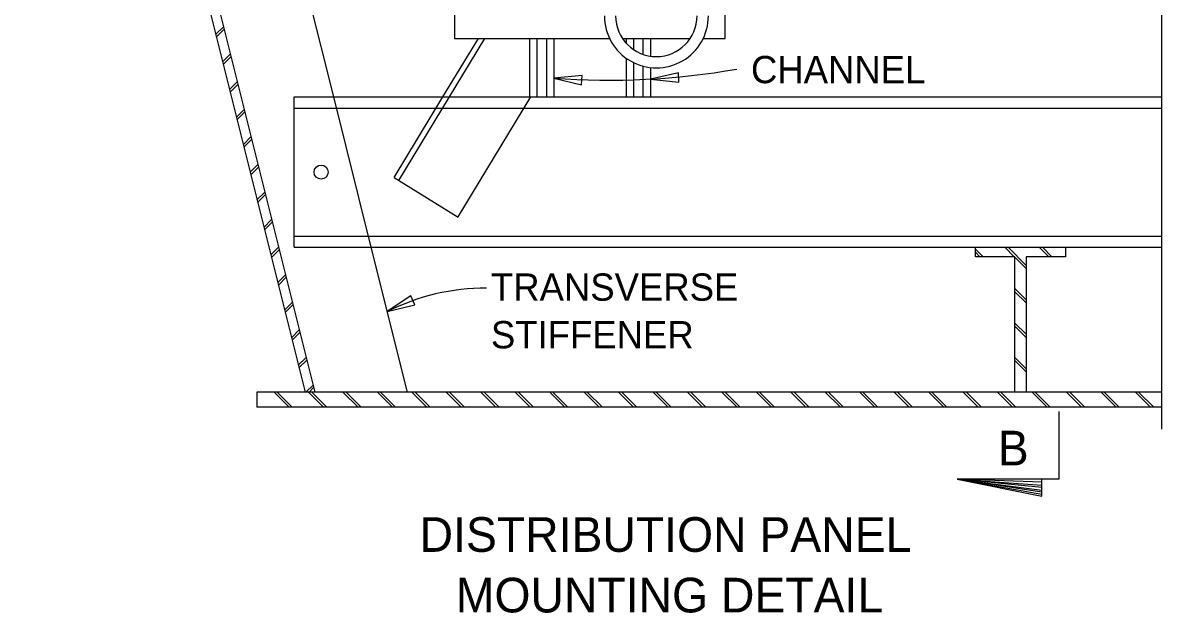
# Model space of a CAD drawing. Extents: x 927736.2 to 927809.6, y 636703.6 to 636757.7.
# Drawn here: x 927758.43 to 927774.19, y 636735.27 to 636743.33 of the extents above; entities that cross this region are included whole.
import ezdxf

# ---------------------------------------------------------------- set-up
doc = ezdxf.new("R2010")
doc.units = 0
for name, color, linetype in [('Default', 7, 'Continuous'), ('DimLines_dp', 7, 'Continuous'), ('Miscellaneous1', 7, 'Continuous'), ('Miscellaneous3', 7, 'Continuous')]:
    doc.layers.add(name, color=color, linetype=linetype)

msp = doc.modelspace()

# ---------------------------------------------------------------- linework, layer by layer
at = {"layer": 'DimLines_dp'}
for p, q in [((927772.357, 636737.056), (927771.201, 636737.099)), ((927771.201, 636737.099), (927772.357, 636737.019)), ((927772.357, 636736.985), (927771.201, 636737.099)), ((927771.201, 636737.099), (927772.357, 636736.951)), ((927772.357, 636736.92), (927771.201, 636737.099)), ((927771.201, 636737.099), (927772.357, 636736.895))]:
    msp.add_line(p, q, dxfattribs=at)
for points in [[(927774, 636737.782), (927774, 636747.055), (927773.809, 636747.055), (927774, 636747.139), (927774.191, 636747.222), (927774, 636747.222), (927774, 636756.677)], [(927772.589, 636738.024), (927772.589, 636737.099), (927771.201, 636737.099), (927772.357, 636736.867), (927772.357, 636737.099)]]:
    msp.add_lwpolyline(points, dxfattribs=at)
for points in [[(927765.688, 636742.581), (927766.067, 636742.487), (927766.077, 636742.617)], [(927767.01, 636742.568), (927767.398, 636742.524), (927767.391, 636742.654)], [(927763.409, 636739.389), (927763.788, 636739.484), (927763.736, 636739.603)]]:
    msp.add_lwpolyline(points, close=True, dxfattribs=at)
msp.add_arc((927766.454, 636752.53), 9.978, 265.6012, 280.0186, dxfattribs=at)
msp.add_ellipse((927764.747, 636736.471), major_axis=(-0.021, -3.238), ratio=0.953713, start_param=3.141601, end_param=3.59647, dxfattribs=at)
at = {"layer": 'Miscellaneous1'}
for p, q in [((927765.354, 636743.124), (927765.354, 636742.324)), ((927765.457, 636743.124), (927765.457, 636742.324)), ((927765.586, 636743.124), (927765.586, 636742.324)), ((927765.688, 636743.124), (927765.688, 636742.324)), ((927766.676, 636743.124), (927766.676, 636743.06)), ((927766.778, 636743.124), (927766.778, 636742.971)), ((927766.907, 636743.124), (927766.907, 636742.906)), ((927767.01, 636743.124), (927767.01, 636742.881)), ((927766.676, 636742.854), (927766.676, 636742.324)), ((927766.778, 636742.793), (927766.778, 636742.324)), ((927766.907, 636742.745), (927766.907, 636742.324)), ((927767.01, 636742.726), (927767.01, 636742.324))]:
    msp.add_line(p, q, dxfattribs=at)
for radius, start, end in [(0.711, 179.9955, 0.0001), (0.557, 180, 0)]:
    msp.add_arc((927767.09, 636743.432), radius, start, end, dxfattribs=at)
at = {"layer": 'Miscellaneous3'}
for p, q in [((927758.434, 636753.706), (927762.288, 636738.29)), ((927758.566, 636753.706), (927762.42, 636738.29)), ((927760.241, 636752.062), (927762.676, 636742.324)), ((927761.066, 636743.177), (927761.172, 636743.283)), ((927761.075, 636743.142), (927761.181, 636743.248)), ((927763.572, 636741.181), (927764.747, 636743.124)), ((927764.173, 636742.324), (927764.657, 636743.124)), ((927761.16, 636742.801), (927761.266, 636742.907)), ((927761.169, 636742.766), (927761.275, 636742.872)), ((927761.254, 636742.424), (927761.36, 636742.53)), ((927761.263, 636742.389), (927761.369, 636742.495)), ((927762.138, 636740.268), (927762.138, 636742.324)), ((927762.138, 636742.323), (927774, 636742.323)), ((927762.675, 636742.324), (927763.189, 636740.268)), ((927763.506, 636741.222), (927764.173, 636742.324)), ((927764.383, 636740.685), (927765.374, 636742.324)), ((927761.349, 636742.047), (927761.455, 636742.153)), ((927761.357, 636742.012), (927761.463, 636742.118)), ((927762.138, 636742.17), (927774, 636742.17)), ((927761.443, 636741.67), (927761.549, 636741.776)), ((927761.452, 636741.635), (927761.558, 636741.741)), ((927761.537, 636741.294), (927761.643, 636741.4)), ((927761.546, 636741.259), (927761.652, 636741.365)), ((927763.506, 636741.222), (927764.379, 636740.679)), ((927761.631, 636740.917), (927761.737, 636741.023)), ((927761.64, 636740.882), (927761.746, 636740.988)), ((927761.725, 636740.54), (927761.831, 636740.646)), ((927761.734, 636740.505), (927761.84, 636740.611)), ((927762.138, 636740.422), (927774, 636740.422)), ((927761.82, 636740.163), (927761.926, 636740.269)), ((927761.828, 636740.128), (927761.934, 636740.234)), ((927762.138, 636740.268), (927774, 636740.268)), ((927763.189, 636740.268), (927763.684, 636738.29)), ((927771.555, 636740.14), (927771.45, 636740.244)), ((927771.511, 636740.14), (927771.45, 636740.201)), ((927771.982, 636740.14), (927771.853, 636740.268)), ((927772.144, 636740.021), (927771.897, 636740.268)), ((927772.453, 636740.14), (927772.324, 636740.268)), ((927772.496, 636740.14), (927772.368, 636740.268)), ((927772.144, 636739.978), (927771.99, 636740.132)), ((927761.914, 636739.787), (927762.02, 636739.893)), ((927761.923, 636739.752), (927762.028, 636739.858)), ((927772.144, 636739.55), (927771.99, 636739.704)), ((927772.144, 636739.507), (927771.99, 636739.661)), ((927762.008, 636739.41), (927762.114, 636739.516)), ((927762.017, 636739.375), (927762.123, 636739.481)), ((927762.102, 636739.033), (927762.208, 636739.139)), ((927762.111, 636738.998), (927762.217, 636739.104)), ((927772.144, 636739.079), (927771.99, 636739.233)), ((927772.144, 636739.036), (927771.99, 636739.19)), ((927762.196, 636738.656), (927762.302, 636738.762)), ((927762.205, 636738.621), (927762.311, 636738.727)), ((927772.144, 636738.608), (927771.99, 636738.763)), ((927772.144, 636738.565), (927771.99, 636738.719)), ((927762.301, 636738.29), (927762.397, 636738.386)), ((927762.344, 636738.29), (927762.405, 636738.351)), ((927763.433, 636738.29), (927761.631, 636738.29)), ((927761.631, 636738.29), (927761.631, 636738.084)), ((927761.631, 636738.29), (927761.631, 636738.084)), ((927762.07, 636738.085), (927761.864, 636738.29)), ((927762.113, 636738.085), (927761.908, 636738.29)), ((927762.541, 636738.085), (927762.335, 636738.29)), ((927762.584, 636738.085), (927762.379, 636738.29)), ((927763.012, 636738.085), (927762.806, 636738.29)), ((927763.055, 636738.085), (927762.85, 636738.29)), ((927763.483, 636738.085), (927763.277, 636738.29)), ((927763.526, 636738.085), (927763.321, 636738.29)), ((927772.067, 636738.29), (927763.434, 636738.29)), ((927763.953, 636738.085), (927763.748, 636738.29)), ((927763.997, 636738.085), (927763.792, 636738.29)), ((927764.424, 636738.085), (927764.219, 636738.29)), ((927764.468, 636738.085), (927764.263, 636738.29)), ((927764.895, 636738.085), (927764.69, 636738.29)), ((927764.939, 636738.085), (927764.734, 636738.29)), ((927765.366, 636738.085), (927765.161, 636738.29)), ((927765.41, 636738.085), (927765.204, 636738.29)), ((927765.837, 636738.085), (927765.632, 636738.29)), ((927765.881, 636738.085), (927765.675, 636738.29)), ((927766.308, 636738.085), (927766.103, 636738.29)), ((927766.352, 636738.085), (927766.146, 636738.29)), ((927766.779, 636738.085), (927766.574, 636738.29)), ((927766.823, 636738.085), (927766.617, 636738.29)), ((927767.25, 636738.085), (927767.045, 636738.29)), ((927767.294, 636738.085), (927767.088, 636738.29)), ((927767.721, 636738.085), (927767.516, 636738.29)), ((927767.765, 636738.085), (927767.559, 636738.29)), ((927768.192, 636738.085), (927767.986, 636738.29)), ((927768.235, 636738.085), (927768.03, 636738.29)), ((927768.663, 636738.085), (927768.457, 636738.29)), ((927768.706, 636738.085), (927768.501, 636738.29)), ((927769.134, 636738.085), (927768.928, 636738.29)), ((927769.177, 636738.085), (927768.972, 636738.29)), ((927769.605, 636738.085), (927769.399, 636738.29)), ((927769.648, 636738.085), (927769.443, 636738.29)), ((927770.076, 636738.085), (927769.87, 636738.29)), ((927770.119, 636738.085), (927769.914, 636738.29)), ((927770.547, 636738.085), (927770.341, 636738.29)), ((927770.59, 636738.085), (927770.385, 636738.29)), ((927771.017, 636738.085), (927770.812, 636738.29)), ((927771.061, 636738.085), (927770.856, 636738.29)), ((927771.488, 636738.085), (927771.283, 636738.29)), ((927771.532, 636738.085), (927771.327, 636738.29)), ((927771.959, 636738.085), (927771.754, 636738.29)), ((927772.003, 636738.085), (927771.798, 636738.29)), ((927771.992, 636738.29), (927771.99, 636738.292)), ((927774, 636738.29), (927772.067, 636738.29)), ((927772.43, 636738.085), (927772.225, 636738.29)), ((927772.474, 636738.085), (927772.268, 636738.29)), ((927772.901, 636738.085), (927772.696, 636738.29)), ((927772.945, 636738.085), (927772.739, 636738.29)), ((927773.372, 636738.085), (927773.167, 636738.29)), ((927773.416, 636738.085), (927773.21, 636738.29)), ((927773.843, 636738.085), (927773.638, 636738.29)), ((927773.887, 636738.085), (927773.681, 636738.29)), ((927761.642, 636738.085), (927761.631, 636738.096)), ((927774, 636738.085), (927761.631, 636738.085))]:
    msp.add_line(p, q, dxfattribs=at)
for points in [[(927767.73, 636743.124), (927768.032, 636743.124), (927768.032, 636751.141), (927765.842, 636751.141)], [(927764.332, 636748.324), (927764.332, 636743.124), (927766.449, 636743.124)], [(927766.626, 636743.124), (927767.553, 636743.124)]]:
    msp.add_lwpolyline(points, dxfattribs=at)
msp.add_lwpolyline([(927771.99, 636738.29), (927771.99, 636740.14), (927771.45, 636740.14), (927771.45, 636740.268), (927772.683, 636740.268), (927772.683, 636740.14), (927772.144, 636740.14), (927772.144, 636738.29)], close=True, dxfattribs=at)
msp.add_circle((927762.508, 636741.296), 0.0964, dxfattribs=at)

# ---------------------------------------------------------------- texts
at = {"layer": 'Default'}
for s, p in [('DISTRIBUTION PANEL', (927763.854, 636736.106)), ('MOUNTING DETAIL', (927764.349, 636735.278))]:
    msp.add_text(s, height=0.4736, dxfattribs=at).set_placement(p)
at = {"layer": 'DimLines_dp'}
for s, height, p in [('CHANNEL', 0.373, (927768.383, 636742.511)), ('TRANSVERSE', 0.373, (927764.829, 636739.538)), ('STIFFENER', 0.373, (927764.829, 636738.887)), ('B', 0.474, (927771.756, 636737.287))]:
    msp.add_text(s, height=height, dxfattribs=at).set_placement(p)

doc.saveas('drawing.dxf')
